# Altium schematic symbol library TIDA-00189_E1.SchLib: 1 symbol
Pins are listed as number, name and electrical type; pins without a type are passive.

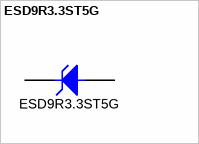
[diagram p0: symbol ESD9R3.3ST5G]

## ESD9R3.3ST5G
designator D?
TVS DIODE 3.3VWM 7.8VC SOD923; Manufacturer: ON Semiconductor; Type: Zener; Unidirectional Channels: 1; Voltage - Reverse Standoff (Typ): 3.3V (Max); Voltage - Breakdown (Min): 4.8V; Voltage - Clamping (Max) @ Ipp: 7.8V; Current - Peak Pulse (10/1000µs): 1A (8/20µs); Power Line Protection: No; Capacitance @ Frequency: 0.5pF @ 1MHz
footprint ESD9R3.3ST5G (TVS DIODE 3.3VWM 7.8VC SOD923)
pins: 1 K, 2 A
